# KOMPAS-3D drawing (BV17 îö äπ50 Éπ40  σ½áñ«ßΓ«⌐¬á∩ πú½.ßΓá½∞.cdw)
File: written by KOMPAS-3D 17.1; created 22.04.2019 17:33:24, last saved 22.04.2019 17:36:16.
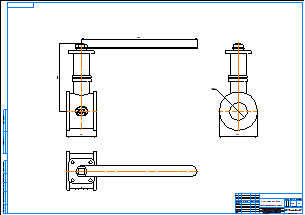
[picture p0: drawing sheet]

Sheet 1: A1, landscape

Title block, sheet 1: name: BV17 МФ Ду50 Ру40 / хладостойкая угл.сталь; material: Внимание! Данный продукт является объектом авторского права ООО «Торговый Дом АДЛ». / Запрещается изменение, копирование, распространение / (в том числе путем копирования на другие сайты и ресурсы в Интернете) / или любое иное использование информации и объектов без предварительного / согласия правообладателя (ООО «Торговый Дом АДЛ»).; mass: 5,83; sheets: 1; organisation: ООО "Торговый дом АДЛ"; sheet format: A1; stored path: \\adlc.lan\data\АДЛ_ПКД\3D-модели\ADL production\Краны шаровые серии BV\BV17 МФ хладостойкая угл.сталь Ру40\KOMPAS 2D\BV17 МФ Ду50 Ру40  хладостойкая угл.сталь.cdw

Views: Вид 1, Проекционный вид 2, Проекционный вид 3
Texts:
  user
Dimensions and other numbers on the sheet: 320; 187; 82; 107; 50; 1:1; 1; 5,83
